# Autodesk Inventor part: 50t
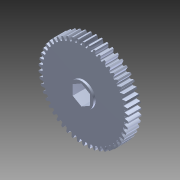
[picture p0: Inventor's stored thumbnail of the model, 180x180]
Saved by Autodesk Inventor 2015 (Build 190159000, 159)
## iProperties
Created: 2014-11
Part Number: 50t
Material: Aluminum 6061
Document SubType Name: Modeling
Designer: Michael
Density: 2.71 g/cm^3
Appearance: Aluminum - Flat
Title: 217-3572-STEP.STEP
Description: STEP AP214
Creation Date: 2013-12-09
Sending System: SolidWorks 2013
Preprocessor: SwSTEP 2.0
Author: Michael
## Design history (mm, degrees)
node "50t1"
node "Combine1"
node "Base1"
